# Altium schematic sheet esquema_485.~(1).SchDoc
size A4
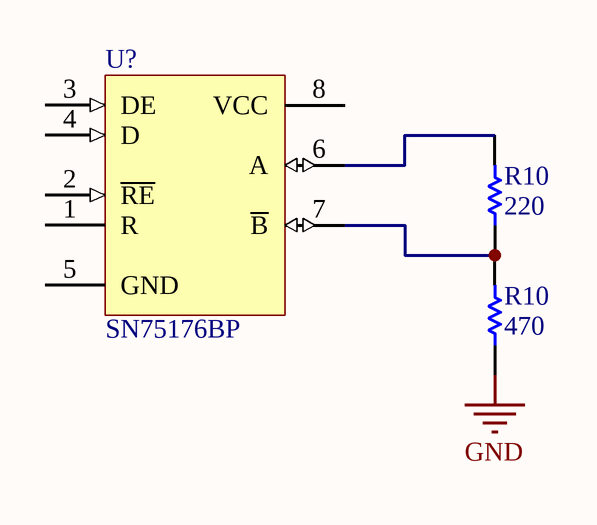
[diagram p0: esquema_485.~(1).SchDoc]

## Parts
(Parts that share a designator on the sheet are numbered #1, #2 ... from top to bottom, then left to right.)
R10#1  value 220  [1005[0402]]  (hidden comment: Carbon 1/8w 5%)
R10#2  value 470  [1005[0402]]  (hidden comment: Carbon 1/8w 5%)
U?  SN75176BP  [P008]

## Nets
GND: R10#2.1
NetR10#1_1: R10#1.1 R10#2.2 U?.7(~{B})
NetR10#1_2: R10#1.2 U?.6(A)

Not connected (* = marked no-connect by the designer): U? 1(R) 2(~{RE}) 3(DE) 4(D) 5(GND) 8(VCC)

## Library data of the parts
R10#1 R10#2 = Res Semi: Semiconductor Resistor
U? = SN75176BP: Differential Bus Transceiver; Note: Receiver Hysteresis of 50mV Typical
